// Mitsubishi GX Works2 project: FlowSort_X_Flow90   PLC: Q13UDV

// global labels: Global1
VAR_GLOBAL CONSTANT
  AlwaysOff : BOOL;
  AlwaysOn : BOOL := TRUE;
END_VAR

PROGRAM FlowSort
VAR
  XFlow90_1 : XFlow90;
END_VAR
; FB BLK START XFlow90(XFlow90_1)
; FB START
; FB_NAME XFlow90
; INSTANCE_NAME XFlow90_1
; FB IN_B:iDivertTypeRev
; FB OUT_qTransferOK:B
; FB IN_B:iTopPosSensor
; FB OUT_qTransfReadyRec:B
; FB IN_B:iBottomPosSensor
; FB OUT_qTransferBusy:B
; FB IN_B:iReset
; FB OUT_qPosSensorError:B
; FB IN_B:iParcelTransfRel
; FB OUT_qConvLinxMRigErr:B
; FB IN_B:iParcelInPosTran
; FB OUT_qConvLinxMLeftEr:B
; FB IN_B:iRunLeft
; FB OUT_qProfinetError:B
; FB IN_B:iRunRight
; FB IN_E:iBeltSpeed
; FB IN_W:iBeltAccelDist
; FB IN_W:iBeltDecelDist
; FB IN_E:iLiftingSpeed
; FB IN_W:iLiftingAccel
; FB IN_W:iLiftingDecel
; FB END
; FB BLK END
27    END
END_PROGRAM

FUNCTION_BLOCK XFlow90
VAR
  sSensorTopPos : BOOL;
  sSensorBottomPos : BOOL;
  sConveyLinxError : BOOL;
  sProfinetError : BOOL;
  sProfinetStatusInstruction : INT;
  sProfinetSetError : BOOL;
  sPositionSensorError : BOOL;
  sTransferNotInDefault : BOOL;
  sTransferPositionOK : BOOL;
  sTransferBusy : BOOL;
  sTransferReadyToReceive : BOOL;
  sMoveTransferUpDown : BOOL;
  sMoveTransferDown : BOOL;
  sTransferInInitialPosition : BOOL;
  sInitFailed : BOOL;
  sErrorMovingDown : BOOL;
  sErrorMovingUp : BOOL;
  sTransferUp : BOOL;
  sMoveRight : BOOL;
  sMoveLeft : BOOL;
  sBeltMotorError : BOOL;
  sPosEdgeTrasnferReleased : BOOL;
  sPosEdgeParcelInPosition : BOOL;
  sNegEdgeMoveLeft : BOOL;
  sNegEdgeMoveRight : BOOL;
  sTransferFinished : BOOL;
  sLiftingSpeedLimit : INT;
  sBeltSpeedLimit : REAL;
END_VAR
VAR_INPUT
  iDivertTypeRev : BOOL;  (* TRUE: TU from secondary track Diverts onto the main track. False: from main track onto secondary *)
  iTopPosSensor : BOOL;  (* Top positioning sensor Top positioning sensor *)
  iBottomPosSensor : BOOL;  (* Bottom positioning sensor *)
  iReset : BOOL;  (* Reset signal from integrator *)
  iParcelTransfRel : BOOL;  (* Parcel is released onto transfer position with destination to be transfered, input from integrator *)
  iParcelInPosTran : BOOL;  (* Parcel is in position to be lifted UP, input from integrator *)
  iRunLeft : BOOL;  (* Run belt left, input from integrator *)
  iRunRight : BOOL;  (* Run belt right, input from integrator *)
  iBeltSpeed : REAL;  (* Belt speed in m/s *)
  iBeltAccelDist : INT;  (* Acceleration distance in mm *)
  iBeltDecelDist : INT;  (* Deceleration distance in mm *)
  iLiftingSpeed : REAL;  (* Lifting speed in RPM *)
  iLiftingAccel : INT;  (* Acceleration in motor pulses *)
  iLiftingDecel : INT;  (* Deceleration in motor pulses *)
END_VAR
VAR_OUTPUT
  qTransferOK : BOOL;  (* Transfer has no errors *)
  qTransfReadyRec : BOOL;  (* Transfer is ready to receive new parcel *)
  qTransferBusy : BOOL;  (* Transfer is occupied and can't accept new parcel *)
  qPosSensorError : BOOL;  (* Sensors could be faulty, hardware inspection is necessary *)
  qConvLinxMRigErr : BOOL;  (* ConveyLinx belt motor is in error *)
  qConvLinxMLeftEr : BOOL;  (* ConveyLinx lifting motor is in error *)
  qProfinetError : BOOL;  (* Profinet conection is lost *)
END_VAR
VAR
  TestingBit : BOOL;
END_VAR
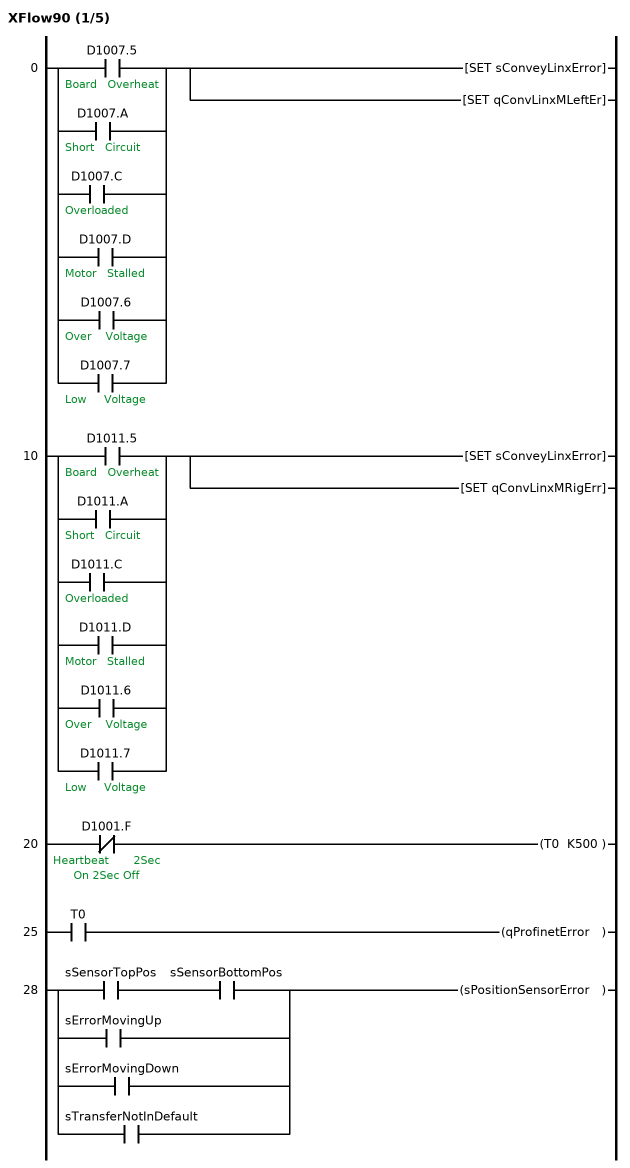
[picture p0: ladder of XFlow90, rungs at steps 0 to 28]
0     LD      D1007.5  ; Board   Overheat
      OR      D1007.A  ; Short   Circuit
      OR      D1007.C  ; Overloaded
      OR      D1007.D  ; Motor   Stalled
      OR      D1007.6  ; Over    Voltage
      OR      D1007.7  ; Low     Voltage
      SET     sConveyLinxError
      SET     qConvLinxMLeftEr
10    LD      D1011.5  ; Board   Overheat
      OR      D1011.A  ; Short   Circuit
      OR      D1011.C  ; Overloaded
      OR      D1011.D  ; Motor   Stalled
      OR      D1011.6  ; Over    Voltage
      OR      D1011.7  ; Low     Voltage
      SET     sConveyLinxError
      SET     qConvLinxMRigErr
20    LDI     D1001.F  ; Heartbeat       2Sec On 2Sec Off
      OUT     T0 K500
25    LD      T0
      OUT     qProfinetError
28    LD      sSensorTopPos
      AND     sSensorBottomPos
      OR      sErrorMovingUp
      OR      sErrorMovingDown
      OR      sTransferNotInDefault
      OUT     sPositionSensorError
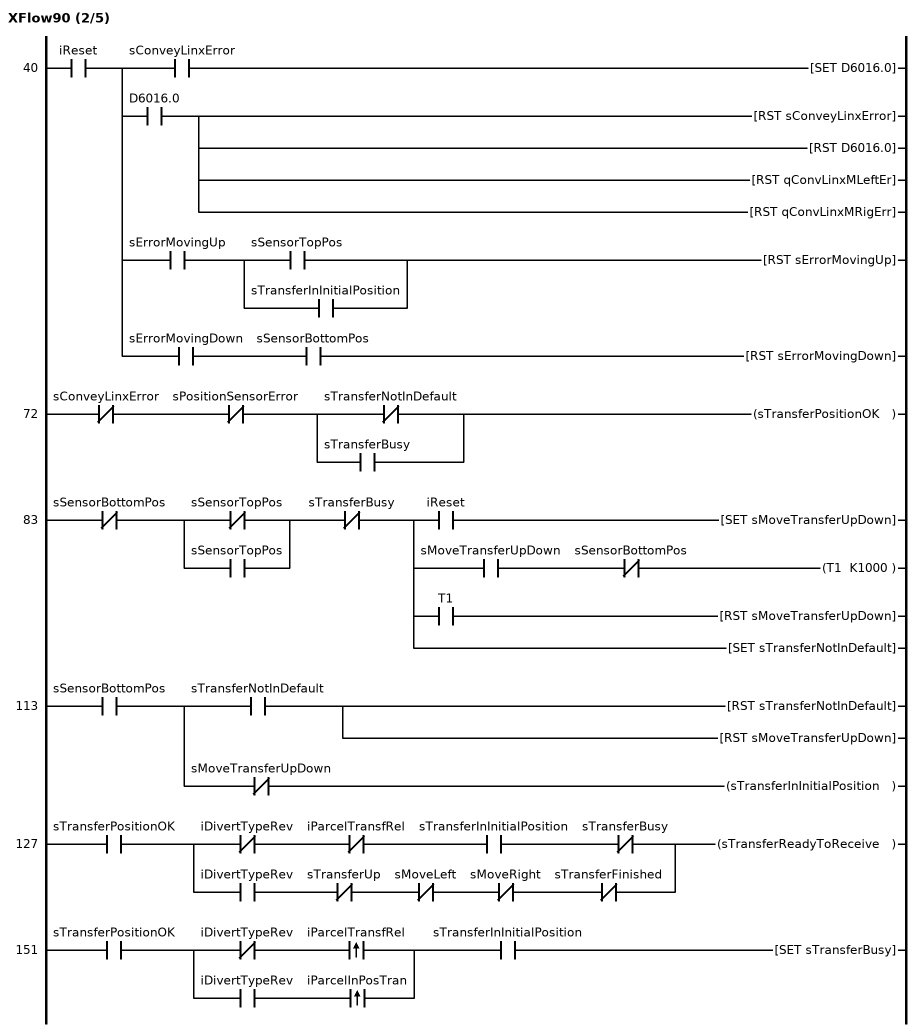
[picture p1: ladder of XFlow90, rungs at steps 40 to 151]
40    LD      iReset
      MPS
      AND     sConveyLinxError
      SET     D6016.0
      MRD
      AND     D6016.0
      RST     sConveyLinxError
      RST     D6016.0
      RST     qConvLinxMLeftEr
      RST     qConvLinxMRigErr
      MRD
      AND     sErrorMovingUp
      LD      sSensorTopPos
      OR      sTransferInInitialPosition
      ANB
      RST     sErrorMovingUp
      MPP
      AND     sErrorMovingDown
      AND     sSensorBottomPos
      RST     sErrorMovingDown
72    LDI     sConveyLinxError
      ANI     sPositionSensorError
      LDI     sTransferNotInDefault
      OR      sTransferBusy
      ANB
      OUT     sTransferPositionOK
83    LDI     sSensorBottomPos
      LDI     sSensorTopPos
      OR      sSensorTopPos
      ANB
      ANI     sTransferBusy
      MPS
      AND     iReset
      SET     sMoveTransferUpDown
      MRD
      AND     sMoveTransferUpDown
      ANI     sSensorBottomPos
      OUT     T1 K1000
      MRD
      AND     T1
      RST     sMoveTransferUpDown
      MPP
      SET     sTransferNotInDefault
113   LD      sSensorBottomPos
      MPS
      AND     sTransferNotInDefault
      RST     sTransferNotInDefault
      RST     sMoveTransferUpDown
      MPP
      ANI     sMoveTransferUpDown
      OUT     sTransferInInitialPosition
127   LD      sTransferPositionOK
      LDI     iDivertTypeRev
      ANI     iParcelTransfRel
      AND     sTransferInInitialPosition
      ANI     sTransferBusy
      LD      iDivertTypeRev
      ANI     sTransferUp
      ANI     sMoveLeft
      ANI     sMoveRight
      ANI     sTransferFinished
      ORB
      ANB
      OUT     sTransferReadyToReceive
151   LD      sTransferPositionOK
      LDI     iDivertTypeRev
      ANDP    iParcelTransfRel
      LD      iDivertTypeRev
      ANDP    iParcelInPosTran
      ORB
      ANB
      AND     sTransferInInitialPosition
      SET     sTransferBusy
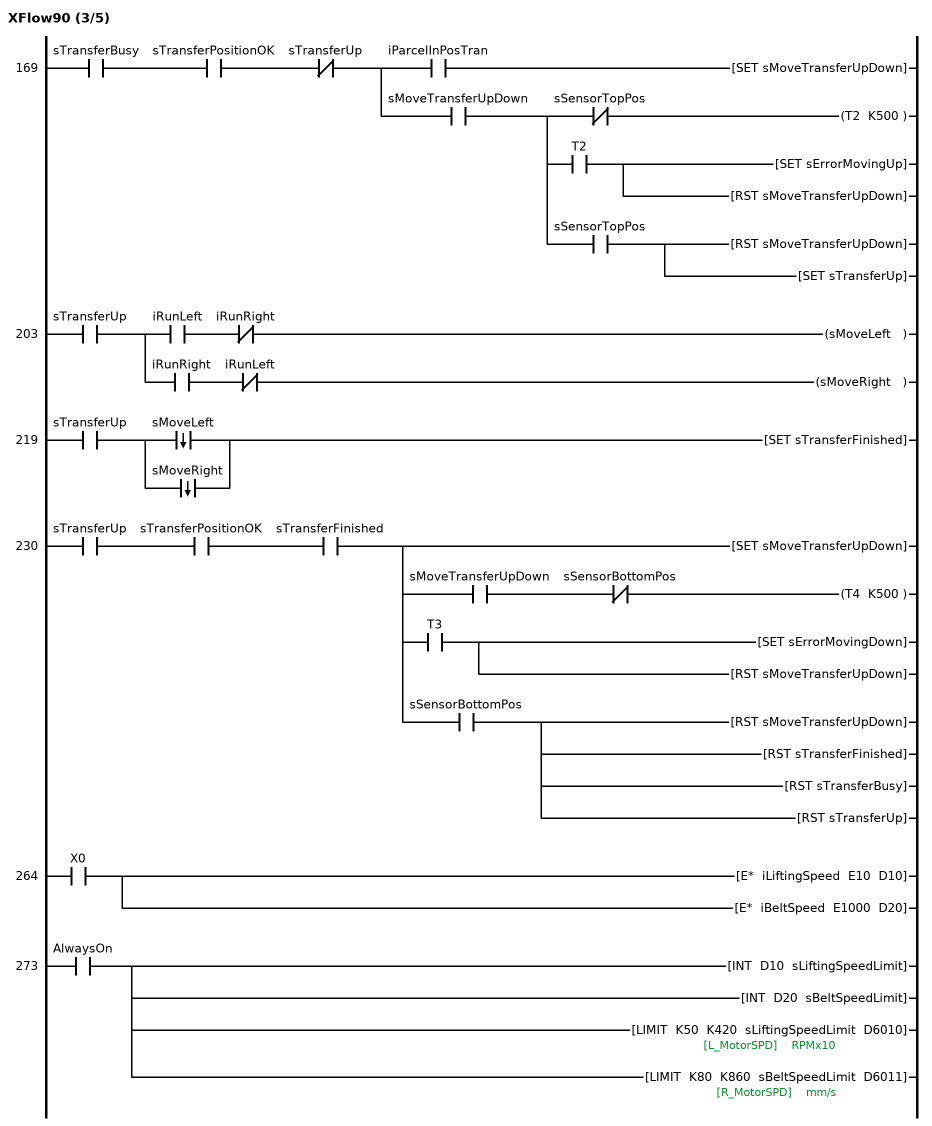
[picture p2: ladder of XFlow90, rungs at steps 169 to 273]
169   LD      sTransferBusy
      AND     sTransferPositionOK
      ANI     sTransferUp
      MPS
      AND     iParcelInPosTran
      SET     sMoveTransferUpDown
      MPP
      AND     sMoveTransferUpDown
      MPS
      ANI     sSensorTopPos
      OUT     T2 K500
      MRD
      AND     T2
      SET     sErrorMovingUp
      RST     sMoveTransferUpDown
      MPP
      AND     sSensorTopPos
      RST     sMoveTransferUpDown
      SET     sTransferUp
203   LD      sTransferUp
      MPS
      AND     iRunLeft
      ANI     iRunRight
      OUT     sMoveLeft
      MPP
      AND     iRunRight
      ANI     iRunLeft
      OUT     sMoveRight
219   LD      sTransferUp
      LDF     sMoveLeft
      ORF     sMoveRight
      ANB
      SET     sTransferFinished
230   LD      sTransferUp
      AND     sTransferPositionOK
      AND     sTransferFinished
      SET     sMoveTransferUpDown
      MPS
      AND     sMoveTransferUpDown
      ANI     sSensorBottomPos
      OUT     T4 K500
      MRD
      AND     T3
      SET     sErrorMovingDown
      RST     sMoveTransferUpDown
      MPP
      AND     sSensorBottomPos
      RST     sMoveTransferUpDown
      RST     sTransferFinished
      RST     sTransferBusy
      RST     sTransferUp
264   LD      X0
      E*      iLiftingSpeed E10 D10
      E*      iBeltSpeed E1000 D20
273   LD      AlwaysOn
      INT     D10 sLiftingSpeedLimit
      INT     D20 sBeltSpeedLimit
      LIMIT   K50 K420 sLiftingSpeedLimit D6010  ; [L_MotorSPD]    RPMx10
      LIMIT   K80 K860 sBeltSpeedLimit D6011  ; [R_MotorSPD]    mm/s
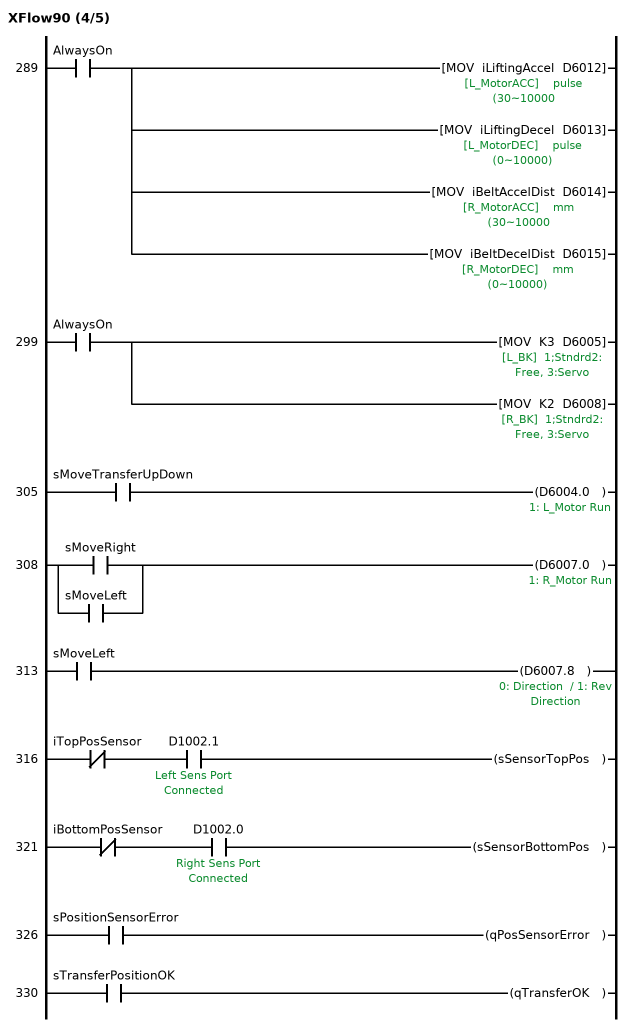
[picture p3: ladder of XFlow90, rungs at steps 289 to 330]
289   LD      AlwaysOn
      MOV     iLiftingAccel D6012  ; [L_MotorACC]    pulse  (30~10000
      MOV     iLiftingDecel D6013  ; [L_MotorDEC]    pulse  (0~10000)
      MOV     iBeltAccelDist D6014  ; [R_MotorACC]    mm     (30~10000
      MOV     iBeltDecelDist D6015  ; [R_MotorDEC]    mm     (0~10000)
299   LD      AlwaysOn
      MOV     K3 D6005  ; [L_BK]  1;Stndrd2:Free, 3:Servo
      MOV     K2 D6008  ; [R_BK]  1;Stndrd2:Free, 3:Servo
305   LD      sMoveTransferUpDown
      OUT     D6004.0  ; 1: L_Motor Run
308   LD      sMoveRight
      OR      sMoveLeft
      OUT     D6007.0  ; 1: R_Motor Run
313   LD      sMoveLeft
      OUT     D6007.8  ; 0: Direction  / 1: Rev Direction
316   LDI     iTopPosSensor
      AND     D1002.1  ; Left Sens Port Connected
      OUT     sSensorTopPos
321   LDI     iBottomPosSensor
      AND     D1002.0  ; Right Sens Port Connected
      OUT     sSensorBottomPos
326   LD      sPositionSensorError
      OUT     qPosSensorError
330   LD      sTransferPositionOK
      OUT     qTransferOK
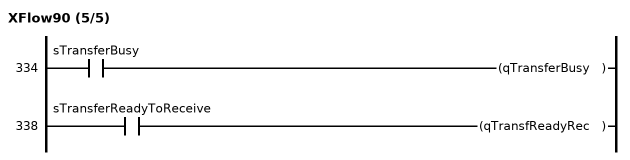
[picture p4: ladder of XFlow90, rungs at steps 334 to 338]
334   LD      sTransferBusy
      OUT     qTransferBusy
338   LD      sTransferReadyToReceive
      OUT     qTransfReadyRec
END_FUNCTION_BLOCK

// device comments not shown above
D1000  ; [Stop CMD_Bit]
D1001  ; [Sensor / Heart B_Bit]
D1002  ; [Sensor Connect Check_Bit]
D1003  ; Motor   Voltage (mV)
D1004  ; Left    Motor   Current (mA)
D1005  ; Left    Motor   Freq... (Hz)
D1006  ; Left    Motor   Temp..  _H_M/L_S
D1007  ; [Left    Motor   Status]
D1008  ; Right    Motor   Current (mA)
D1009  ; Right    Motor   Freq... (Hz)
D1010  ; Right   Motor   Temp..  _H_M/L_S
D1011  ; Right    Motor   Status]
D1012  ; [Left Motor Port Digital]
D1013  ; [Right Motor Port Digital]
D1019  ; [Left   Motor   Servo   Pos.]
D1020  ; [Right  Motor   Servo   Pos.]
D1021  ; [Left   Motor   Servo   Status.]
D1022  ; [Right  Motor   Servo   Status.]
D1023  ; [Left   Motor   Real SPD]
D1024  ; [Right  Motor   Real SPD]
D6000  ; [Modbus Write   Address]
D6003  ; [Sensor Port /  Digital Output]
D6004  ; [Left   Motor   Run]
D6007  ; [Right  Motor   Run]
D6016  ; [Clear  Motor   Err]    1:Reset
D6019  ; [Sensor Mask]
D6023  ; [L_ServoPositionCMD]-32767~32767
D6024  ; [L_Servo CMD]   SET"0"  / RUN
D6025  ; [R_ServoPositionCMD]-32767~32767
D6026  ; [R_Servo CMD]   SET"0"  / RUN
D1000.5  ; Stop activ on another module
D1000.6  ; Stop activ. Lost comm Connection
D1000.7  ; Stop activ. Lost PLC Connection
D1000.A  ; Stop activ. Stop cmd from PLC
D1001.0  ; Left Sens Port - Aux (M8 Pin2)
D1001.2  ; Right Sens Port - Aux (M8 Pin2
D1001.4  ; Left Sens Port - Signal (M8 Pin4
D1001.6  ; Right Sens Port - Signa (M8 Pin4
D1007.0  ; Motor   Status L (00-Brk/01-CCW)
D1007.1  ; Motor   Status H(10-CW /11-NoBrk
D1007.2  ; Port in Digital Mode
D1007.8  ; Overheated
D1007.9  ; Max.    Torque
D1007.B  ; Motor   Not     Connected
D1007.E  ; Hall    Sensor  Error
D1007.F  ; Motor   Not Used
D1011.0  ; Motor   Status L (00-Brk/01-CCW)
D1011.1  ; Motor   Status H(10-CW /11-NoBrk
D1011.2  ; Port in Digital Mode
D1011.8  ; Overheated
D1011.9  ; Max.    Torque
D1011.B  ; Motor   Not     Connected
D1011.E  ; Hall    Sensor  Error
D1011.F  ; Motor   Not Used
D1012.C  ; Short Circuit Error
D1012.D  ; Over Current (1A over)
D1013.C  ; Short Circuit Error
D1013.D  ; Over Current (1A over)
D1021.0  ; ServoRunCMD     Complete.(on)
D1022.0  ; ServoRunCMD     Complete.(on)
D1023.E  ; 14bit   Motor   Max SPD
D1023.F  ; 14bit   Motor   Min SPD
D1024.E  ; 14bit   Motor   Max SPD
D1024.F  ; 14bit   Motor   Min SPD
D6003.0  ; 1: Left Pin2 On 0: Left Pin2 Off
D6003.1  ; 1: Rght Pin2 On 0: Rght Pin2 Off
D6003.5  ; 1: Left Pin 2   Output
D6003.6  ; 1: RightPin 2   Output
D6004.8  ; 0: Direction  / 1: Rev Direction
D6024.0  ; 1: Set   Positon "0"
D6024.1  ; 1: Servo Run CMD
D6026.0  ; 1: Set   Positon "0"
D6026.1  ; 1: Servo Run CMD
